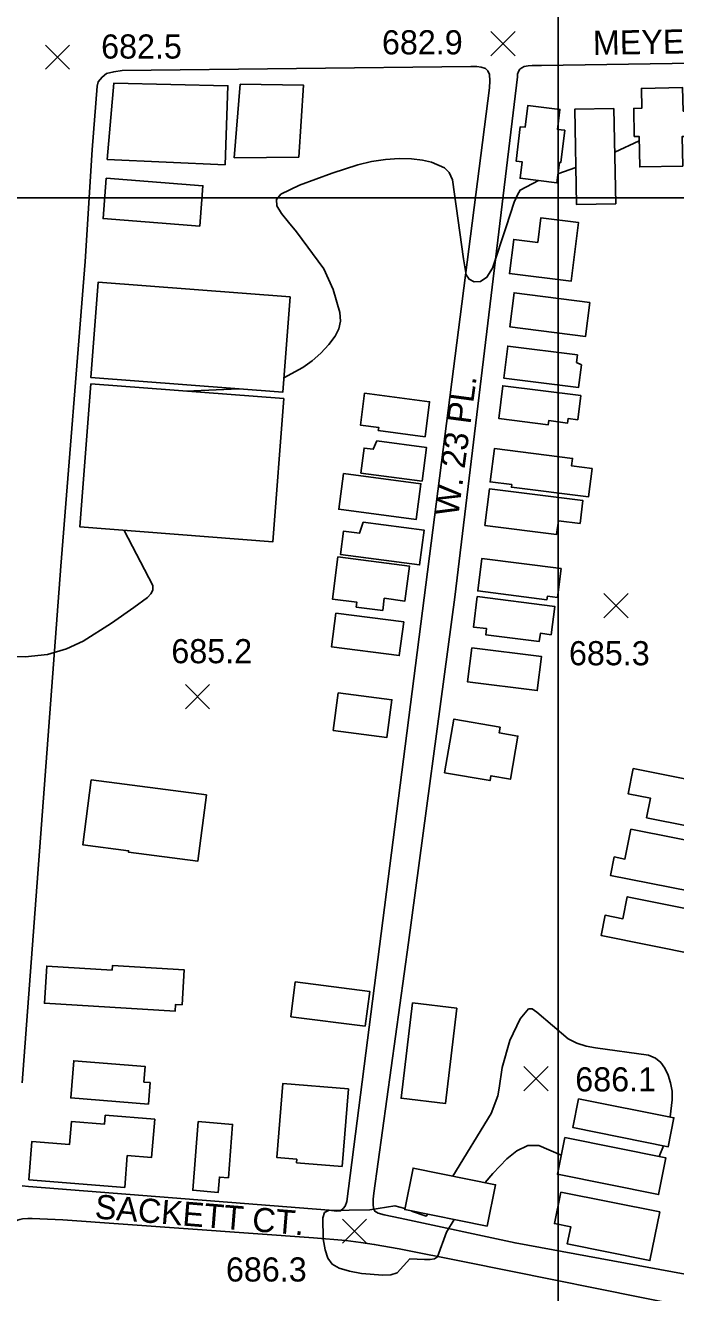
# Model space of a CAD drawing. Extents: x 79600 to 91800, y 75600 to 84400.
# Drawn here: x 84369 to 84773, y 76319 to 77107 of the extents above; entities that cross this region are included whole.
import ezdxf

# ---------------------------------------------------------------- set-up
doc = ezdxf.new("R2010")
doc.units = 0
for name, color, linetype in [('080-085$0$BLDG', 7, 'Continuous'), ('080-085$0$GRID', 7, 'Continuous'), ('080-085$0$INTER', 7, 'Continuous'), ('080-085$0$ROAD', 7, 'Continuous'), ('080-085$0$ROAD-NAME', 7, 'Continuous'), ('080-085$0$SPOTMARK', 7, 'Continuous'), ('080-085$0$SPOTS', 7, 'Continuous'), ('080-090$0$TI_BORDER', 7, 'Continuous')]:
    doc.layers.add(name, color=color, linetype=linetype)

# ---------------------------------------------------------------- blocks, each defined once
blk = doc.blocks.new('080-085$0$SPOTS')
at = {"layer": '080-085$0$SPOTMARK'}
for p, q in [((-0.5, -0.5), (0.5, 0.5)), ((-0.5, 0.5), (0.5, -0.5))]:
    blk.add_line(p, q, dxfattribs=at)

msp = doc.modelspace()

# ---------------------------------------------------------------- linework, layer by layer
at = {"layer": '080-085$0$BLDG'}
for points in [[(84419.59, 77023.72), (84492.93, 77020.51), (84494.66, 77069.65), (84423.78, 77071.15)], [(84538.84, 77025.21), (84541.61, 77070.03), (84502.42, 77070.5), (84498.68, 77024.85)], [(84777.59, 77053.76), (84780.65, 77053.82), (84780.97, 77038.04), (84777.01, 77037.96), (84777.38, 77019.65), (84750.66, 77019.12), (84750.28, 77038.15), (84747.28, 77038.09), (84746.93, 77055.51), (84751.95, 77055.61), (84751.71, 77067.98), (84777.3, 77068.48)], [(84700.74, 77021.94), (84701.6, 77021.83), (84704.09, 77041.93), (84699.51, 77042.49), (84701.05, 77054.93), (84681.15, 77057.4), (84679.46, 77043.76), (84676.42, 77044.13), (84673.77, 77022.8), (84677.57, 77022.32), (84676.3, 77012.08), (84699.17, 77009.24)], [(84735.73, 76996.17), (84711.42, 76995.69), (84710.25, 77054.96), (84734.56, 77055.44)], [(84419.08, 77012.11), (84479.15, 77007.47), (84477.21, 76982.36), (84417.15, 76987)], [(84687.38, 76972.19), (84689.28, 76987.55), (84712.55, 76984.66), (84708, 76948.01), (84669.68, 76952.77), (84672.33, 76974.06)], [(84533.32, 76938.3), (84528.74, 76878.99), (84409.53, 76888.19), (84414.11, 76947.5)], [(84719.7, 76934.94), (84672.53, 76940.89), (84669.86, 76919.74), (84717.03, 76913.79)], [(84711.29, 76897.53), (84711.9, 76902.29), (84668.64, 76907.75), (84666.13, 76887.85), (84712.61, 76881.99), (84714.39, 76896.08)], [(84409.55, 76884.32), (84402.68, 76795.3), (84522.58, 76786.04), (84529.45, 76875.06)], [(84588.18, 76855.17), (84588.44, 76857.19), (84577.1, 76858.67), (84579.68, 76878.4), (84620.08, 76873.12), (84617.23, 76851.37)], [(84712.14, 76861.87), (84706.13, 76862.63), (84705.79, 76859.91), (84694.16, 76861.38), (84693.84, 76858.88), (84663.01, 76862.77), (84665.58, 76883.08), (84714.05, 76876.96)], [(84587.35, 76848.78), (84584.99, 76843.6), (84579.37, 76844.33), (84577.33, 76828.77), (84615.35, 76823.8), (84618.09, 76844.76)], [(84721.03, 76831.58), (84708.31, 76833.19), (84708.9, 76837.89), (84660.3, 76844.02), (84657.69, 76823.31), (84671.14, 76821.61), (84670.93, 76819.97), (84718.81, 76813.94)], [(84566.47, 76828.5), (84563.57, 76806.31), (84611.78, 76800.01), (84614.68, 76822.2)], [(84713.6, 76797.44), (84700.1, 76799.15), (84699.02, 76790.63), (84654.45, 76796.25), (84657.32, 76819.03), (84715.4, 76811.7)], [(84578.77, 76798.28), (84576.57, 76791.41), (84566.65, 76792.71), (84564.75, 76778.14), (84613.85, 76771.72), (84616.68, 76793.33)], [(84563.12, 76776.74), (84559.68, 76750.46), (84574.84, 76748.47), (84574.46, 76745.52), (84590.94, 76743.36), (84591.92, 76750.92), (84604.69, 76749.25), (84607.52, 76770.94)], [(84699.55, 76751.46), (84693.28, 76752.26), (84693, 76750.08), (84649.95, 76755.51), (84652.49, 76775.62), (84701.81, 76769.4)], [(84695.59, 76728.32), (84688.91, 76729.16), (84688.27, 76724.1), (84654.98, 76728.3), (84655.45, 76732.06), (84647.32, 76733.08), (84649.7, 76751.96), (84697.81, 76745.89)], [(84561.74, 76741.78), (84559, 76720.8), (84601.22, 76715.28), (84603.96, 76736.26)], [(84646.38, 76720.18), (84689.69, 76714.71), (84687.02, 76693.52), (84643.71, 76698.99)], [(84563.2, 76692.26), (84560.13, 76668.82), (84593.53, 76664.45), (84596.6, 76687.9)], [(84663.83, 76670.86), (84663.22, 76667.31), (84674.91, 76665.29), (84670.27, 76638.48), (84658.14, 76640.59), (84657.62, 76637.56), (84629.4, 76642.45), (84635.18, 76675.82)], [(84746.54, 76645.04), (84743.45, 76629.46), (84757.32, 76626.71), (84754.89, 76614.49), (84808.23, 76603.92), (84813.74, 76631.72)], [(84409.73, 76638.02), (84404.46, 76597.73), (84432.99, 76594), (84432.87, 76593.11), (84475.95, 76587.48), (84481.34, 76628.66)], [(84745.17, 76607.43), (84741.49, 76588.84), (84734.86, 76590.15), (84732.56, 76578.59), (84782.08, 76568.77), (84783.14, 76574.12), (84797.6, 76571.25), (84802.52, 76596.06)], [(84780.87, 76550.89), (84782.2, 76557.52), (84742.96, 76565.38), (84740.21, 76551.66), (84729.16, 76553.88), (84726.64, 76541.31), (84786.37, 76529.33), (84790.31, 76549)], [(84422.72, 76519.79), (84422.89, 76522.61), (84467.54, 76519.94), (84466.23, 76498.19), (84462.22, 76498.43), (84461.97, 76494.26), (84380.68, 76499.13), (84382.06, 76522.23)], [(84580.11, 76484.96), (84533.88, 76490.79), (84536.61, 76512.39), (84582.84, 76506.56)], [(84637.09, 76496.09), (84629.93, 76436.79), (84602.35, 76440.12), (84609.52, 76499.42)], [(84442.45, 76450.12), (84446.35, 76449.81), (84445.28, 76436.47), (84397, 76440.36), (84398.86, 76463.44), (84443.23, 76459.87)], [(84537.28, 76400.01), (84537.46, 76402.21), (84525.13, 76403.2), (84528.83, 76449.23), (84569.6, 76445.95), (84565.71, 76397.72)], [(84712.71, 76439.84), (84709.11, 76421.86), (84768.35, 76409.98), (84771.96, 76427.96)], [(84432.15, 76404.57), (84447.27, 76403.36), (84449.18, 76427.06), (84418.47, 76429.53), (84418.03, 76424.09), (84397.5, 76425.75), (84396.34, 76411.35), (84372.89, 76413.23), (84370.97, 76389.43), (84430.55, 76384.63)], [(84494.97, 76390.69), (84489.46, 76391.13), (84488.69, 76381.59), (84472.82, 76382.87), (84476.26, 76425.59), (84497.65, 76423.87)], [(84704.03, 76415.6), (84699.47, 76392.87), (84762.36, 76380.26), (84766.92, 76402.99)], [(84655.94, 76360.54), (84604.57, 76370.84), (84609.75, 76396.64), (84661.11, 76386.34)], [(84701.56, 76381.73), (84697.65, 76362.23), (84707.8, 76360.19), (84705.66, 76349.5), (84757.05, 76339.19), (84763.1, 76369.39)]]:
    msp.add_lwpolyline(points, close=True, dxfattribs=at)
at = {"layer": '080-085$0$GRID'}
msp.add_line((85000, 77000), (80000, 77000), dxfattribs=at)
at = {"layer": '080-085$0$INTER'}
for p, q in [((84735.1, 77028.21), (84750.34, 77035.39)), ((84699.86, 77014.82), (84710.97, 77018.74)), ((84468.73, 76879.75), (84501.47, 76881.09)), ((84762.65, 76403.84), (84765.48, 76410.56))]:
    msp.add_line(p, q, dxfattribs=at)
for points in [[(84529.44, 76888.01), (84541.33, 76894.49), (84546.98, 76898.48), (84552.51, 76903.37), (84557.43, 76908.67), (84561.27, 76913.82), (84563.66, 76918.45), (84564.61, 76923.14), (84564.21, 76928.66), (84560.14, 76942.95), (84554.34, 76955.84), (84537.37, 76978.72), (84532.31, 76984.81), (84527.93, 76990.2), (84525.11, 76994.84), (84524.81, 76998.79), (84527.64, 77002.15), (84539.1, 77007.71), (84559.54, 77015.27), (84575.43, 77020.4), (84583.97, 77022.43), (84592.68, 77023.72), (84601.15, 77024.28), (84608.91, 77024.13), (84615.6, 77023.34), (84621.18, 77022.06), (84629.36, 77018.48), (84632.16, 77015.63), (84634.28, 77011.17), (84641.1, 76962), (84642.72, 76952.14), (84644.6, 76949.34), (84647.76, 76947.72), (84651.69, 76947.87), (84655.65, 76950.53), (84659.06, 76956.13), (84667.65, 76981.97), (84672.73, 76997.13), (84674.63, 77001.78), (84676.39, 77004.72), (84687.69, 77010.67)], [(84330.29, 76768.47), (84330.31, 76752.14), (84330.72, 76738.51), (84331.24, 76732.82), (84332.1, 76727.77), (84333.63, 76723.26), (84337.08, 76719.45), (84343.95, 76716.57), (84355.07, 76714.83), (84368.71, 76714.55), (84382.47, 76716.05), (84394.45, 76719.49), (84404.74, 76724.33), (84422.38, 76735.49), (84436.33, 76745.2), (84444.65, 76751.39), (84446.88, 76753.72), (84448.01, 76756.07), (84448, 76758.87), (84430.18, 76793.18)], [(84769.51, 76428.45), (84770.85, 76439.22), (84770.75, 76444.43), (84769.86, 76449.65), (84768.28, 76454.55), (84766.22, 76458.83), (84763.76, 76462.28), (84760.57, 76464.96), (84756.16, 76466.98), (84723.25, 76471.4), (84717.28, 76472.52), (84711.62, 76474.4), (84706.17, 76477.14), (84686.7, 76493.63), (84683.85, 76495.69), (84681.6, 76495.79), (84676.36, 76489.55), (84669.94, 76475.98), (84665.22, 76459.23), (84663.21, 76446.28), (84662.55, 76441.57), (84658.31, 76430.67), (84634.51, 76391.68)], [(84654.51, 76387.67), (84659.3, 76393.26), (84668.11, 76402.47), (84674.32, 76407.5), (84681.09, 76410.64), (84687.86, 76410.72), (84701.83, 76404.64)], [(84604.7, 76371.48), (84598.42, 76373.32), (84582.85, 76370.75), (84557.25, 76370.32), (84554.78, 76369.07), (84553.69, 76365.79), (84553.97, 76352.8), (84555.06, 76345.96), (84556.74, 76340.73), (84559.49, 76337.03), (84563.9, 76334.43), (84570.27, 76332.55), (84577.67, 76331.25), (84591.02, 76330.06), (84595.94, 76330.34), (84599.85, 76331.52), (84607.73, 76340.23)], [(84618.93, 76367.96), (84617.93, 76366.7), (84608.84, 76369.98)], [(84607.73, 76340.23), (84616.81, 76339.87), (84620.34, 76339.93), (84623.02, 76340.32), (84624.97, 76341.47), (84630.65, 76356.82), (84635.38, 76364.66)]]:
    msp.add_lwpolyline(points, dxfattribs=at)
at = {"layer": '080-085$0$ROAD'}
for points in [[(84778.82, 76330.64), (84673.18, 76350.12), (84601.69, 76365.62), (84591.75, 76367.71), (84588.02, 76368.6), (84586.1, 76369.88), (84585.43, 76371.14), (84584.91, 76373.5), (84584.97, 76377.38), (84585.31, 76381.11), (84606.95, 76536.98), (84635.73, 76751.74), (84674.63, 77075.19), (84674.79, 77076.85), (84675.37, 77078.5), (84676.22, 77079.87), (84677.35, 77080.83), (84678.74, 77081.5), (84681.38, 77082.01), (84683.74, 77082.11), (84689.55, 77082.16), (84919.49, 77085.69)], [(84366.87, 76449.69), (84390.91, 76770.87), (84406.01, 76960.36), (84410.4, 77029.67), (84413.36, 77069.37), (84414.1, 77072.13), (84416.5, 77075), (84419.3, 77077.17), (84423.75, 77078.35), (84429.02, 77079.1), (84645.65, 77081.59), (84649.52, 77081.53), (84652.15, 77081.21), (84654.9, 77080.34), (84656.27, 77078.93), (84657.34, 77076.56), (84657.42, 77072.68), (84657.35, 77068.39), (84568.61, 76375.96), (84567.6, 76372.93), (84566.33, 76371.57), (84564.78, 76370.21), (84563.26, 76370.09), (84562.15, 76369.97), (84557.73, 76370.59), (84370.86, 76385.23), (84366.72, 76385.71)], [(84351.83, 76255.08), (84359.22, 76357.3), (84360.23, 76360.19), (84360.66, 76361.29), (84361.51, 76362.67), (84362.78, 76363.75), (84363.89, 76364.29), (84365.43, 76364.82), (84367.09, 76365.21), (84370.42, 76365.3), (84373.05, 76365.26), (84392.15, 76364.55), (84547.9, 76353.29), (84568.1, 76351.74), (84577.22, 76350.35), (84585.65, 76349.25), (84601.12, 76346.52), (84641.71, 76338.42), (84779.62, 76310.54)]]:
    msp.add_lwpolyline(points, dxfattribs=at)
at = {"layer": '080-090$0$TI_BORDER'}
msp.add_lwpolyline([(84700, 80300), (91700, 80300), (91700, 75700), (84700, 75700)], close=True, dxfattribs=at)

# ---------------------------------------------------------------- block references
at = {"layer": '080-085$0$SPOTMARK', "xscale": 15, "yscale": 15}
for p in [(84665.65, 77095.79), (84388.76, 77087.4), (84735.96, 76746.33), (84475.81, 76689.78), (84686.19, 76452.26), (84573.36, 76357.41)]:
    msp.add_blockref('080-085$0$SPOTS', p, dxfattribs=at)

# ---------------------------------------------------------------- texts
at = {"layer": '080-085$0$ROAD-NAME'}
for s, rotation, p in [('MEYER AVE.', 0.96665, (84721.68, 77088.75)), ('W. 23 PL.', 82.45782, (84637.84, 76801.36)), ('SACKETT CT.', 355.36255, (84411.61, 76365.43))]:
    msp.add_text(s, height=15, rotation=rotation, dxfattribs=at).set_placement(p)
at = {"layer": '080-085$0$SPOTS'}
for s, p in [('682.5', (84415.9, 77086.5)), ('682.9', (84590.46, 77089.11)), ('685.2', (84459.56, 76710.56)), ('685.3', (84706.69, 76709.3)), ('686.1', (84710.61, 76444.35)), ('686.3', (84493.48, 76326.16))]:
    msp.add_text(s, height=15, dxfattribs=at).set_placement(p)

doc.saveas('drawing.dxf')
